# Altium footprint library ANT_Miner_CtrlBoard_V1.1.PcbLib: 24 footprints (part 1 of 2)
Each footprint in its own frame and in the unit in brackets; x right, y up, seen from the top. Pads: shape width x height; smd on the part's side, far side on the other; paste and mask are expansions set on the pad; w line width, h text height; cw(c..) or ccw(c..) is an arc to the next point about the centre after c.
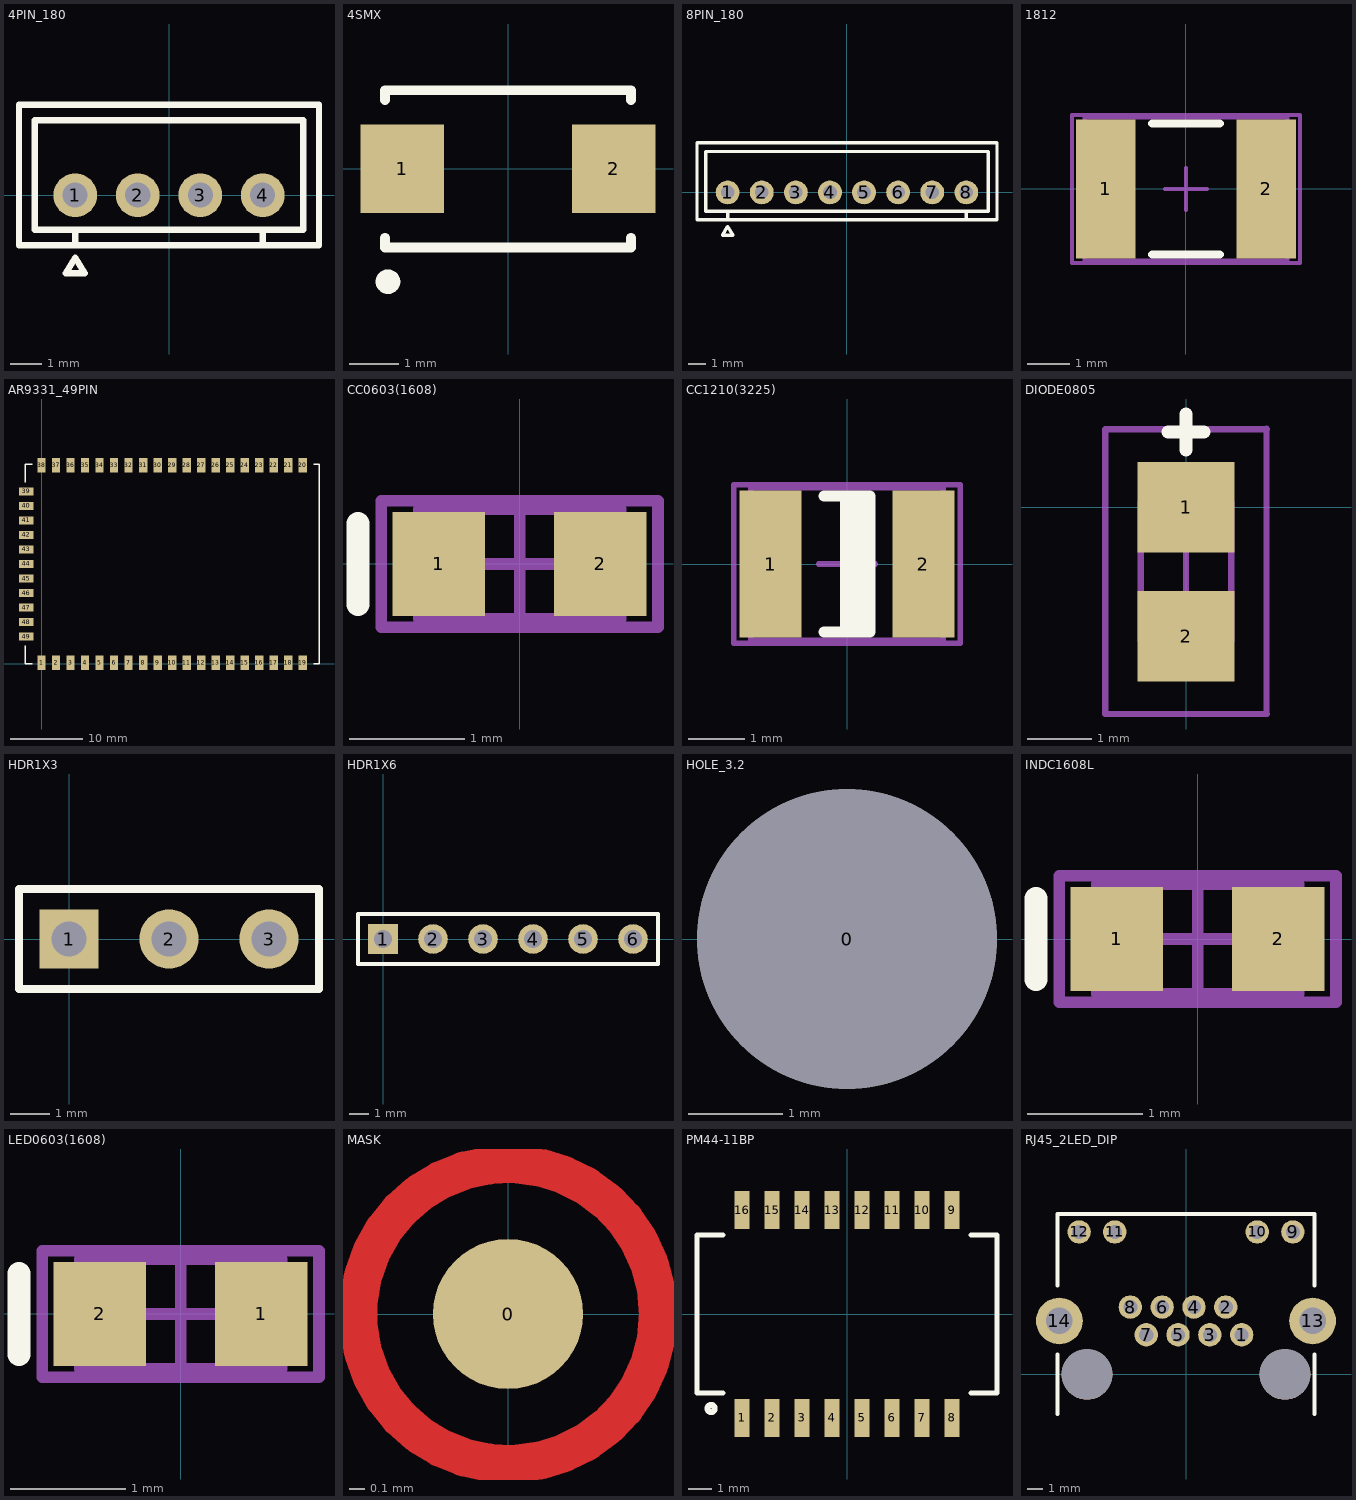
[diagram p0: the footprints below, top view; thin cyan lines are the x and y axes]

## 4PIN_180 [mm]
height 6.8
pads (4):
  round 1.4 hole 0.8: 1(-3,0) 2(-1,0) 3(1,0) 4(3,0)
Top Overlay:
  lines w0.203: -3,-1.6 -3,-1.1 ; 3,-1.6 3,-1.1 ; -4.8,-1.6 4.8,-1.6 4.8,2.9 -4.8,2.9 -4.8,-1.6 ; -4.3,-1.1 4.3,-1.1 4.3,2.4 -4.3,2.4 -4.3,-1.1 ; -3.3,-2.5 -3,-2 -2.7,-2.5 -3.3,-2.5
3D body: height 6.1, standoff -2.2, extent -5,-1.8 5,3

## 4SMX [mm]
height 18.15
pads (2):
  rect 1.7x1.8 smd: 1(-2.15,0) 2(2.15,0)
Top Overlay:
  circle w0.25: c-2.441,-2.293 r0.125
  lines w0.2: -2.5,-1.4 -2.5,-1.6 2.5,-1.6 2.5,-1.4 ; -2.5,1.4 -2.5,1.6 2.5,1.6 2.5,1.4

## 8PIN_180 [mm]
height 6.8
pads (8):
  round 1.4 hole 0.8: 1(-7,0) 2(-5,0) 3(-3,0) 4(-1,0) 5(1,0) 6(3,0) 7(5,0) 8(7,0)
Top Overlay:
  lines w0.203: -7,-1.6 -7,-1.1 ; 7,-1.6 7,-1.1 ; -8.8,-1.6 -8.8,2.9 8.8,2.9 8.8,-1.6 -8.8,-1.6 ; -8.3,-1.1 -8.3,2.4 8.3,2.4 8.3,-1.1 -8.3,-1.1 ; -7.3,-2.5 -6.7,-2.5 -7,-2 -7.3,-2.5
3D body: height 6.1, standoff -2.2, extent -9,-1.8 9,3

## 1812 [mm] "Chip Capacitor, Body 4.5x3.2mm, IPC High Density"
height 1.4
pads (2):
  rect 1.4x3.3 smd: 1(-1.9,0) 2(1.9,0)
Top Overlay:
  lines w0.2: -0.8,-1.55 0.8,-1.55 ; -0.8,1.55 0.8,1.55
Mechanical 13:
  lines w0.1: -2.4,-1.7 2.4,-1.7 2.4,1.7 -2.4,1.7 -2.4,-1.7
Mechanical 15:
  lines w0.1: -0.5,0 0.5,0 ; 0,-0.5 0,0.5 ; -2.7,-1.75 2.7,-1.75 2.7,1.75 -2.7,1.75 -2.7,-1.75
3D body: height 1.4, standoff 0, extent -2.4,-1.7 2.4,1.7

## AR9331_49PIN [mm] "AR9331 49PIN"
height 2.5
pads (49):
  rect 1.143x2 smd: 1(0,0.158) 2(2,0.158) 3(4,0.158) 4(6,0.158) 5(8,0.158) 6(10,0.158) 7(12,0.158) 8(14,0.158) 9(16,0.158) 10(18,0.158) 11(20,0.158) 12(22,0.158) 13(24,0.158) 14(26,0.158) 15(28,0.158) 16(30,0.158) 17(32,0.158) 18(34,0.158) 19(36,0.158) 20(36,27.341) 21(34,27.341) 22(32,27.341) 23(30,27.341) 24(28,27.341) 25(26,27.341) 26(24,27.341) 27(22,27.341) 28(20,27.341) 29(18,27.341) 30(16,27.341) 31(14,27.341) 32(12,27.341) 33(10,27.341) 34(8,27.341) 35(6,27.341) 36(4,27.341) 37(2,27.341) 38(0,27.341)
  rect 2x1.146 smd: 39(-2.11,23.75) 40(-2.11,21.75) 41(-2.11,19.75) 42(-2.11,17.75) 43(-2.11,15.75) 44(-2.11,13.75) 45(-2.11,11.75) 46(-2.11,9.75) 47(-2.11,7.75) 48(-2.11,5.75) 49(-2.11,3.75)
Top Overlay:
  lines w0.203: -2.25,2.5 -2.25,0 -1.25,0 ; -2.25,25 -2.25,27.5 -1.25,27.5 ; 37.5,0 38.25,0 38.25,27.5 37.5,27.5

## CC0603(1608) [mm] "Chip Capacitor, Body 1.6x0.8mm, IPC High Density"
height 0.85
pads (2):
  rect 0.8x0.9 smd: 1(-0.7,0) 2(0.7,0)
Top Overlay:
  lines w0.2: -1.4,-0.35 -1.4,0.35
Mechanical 13:
  lines w0.1: -0.875,-0.475 0.875,-0.475 0.875,0.475 -0.875,0.475 -0.875,-0.475
Mechanical 15:
  lines w0.1: -0.475,0 0.475,0 ; 0,-0.475 0,0.475 ; -1.2,-0.55 1.2,-0.55 1.2,0.55 -1.2,0.55 -1.2,-0.55
3D body: height 0.85, standoff 0, extent -0.875,-0.475 0.875,0.475

## CC1210(3225) [mm] "Chip Capacitor, Body 3.2x2.5mm, IPC High Density"
height 1.35
pads (2):
  rect 1.1x2.6 smd: 1(-1.35,0) 2(1.35,0)
Top Overlay:
  rectangle: -0.125,-1.2 0.425,1.2
  lines w0.2: -0.4,-1.2 0.4,-1.2 0.4,1.2 -0.4,1.2
Mechanical 13:
  lines w0.1: -1.7,-1.35 -1.7,1.35 1.7,1.35 1.7,-1.35 -1.7,-1.35
Mechanical 15:
  lines w0.1: -0.5,0 0.5,0 ; 0,-0.5 0,0.5 ; -2,-1.4 -2,1.4 2,1.4 2,-1.4 -2,-1.4
3D body: height 1.35, standoff 0, extent -1.7,-1.35 1.7,1.35

## DIODE0805 [mm]
height 0.9
pads (2):
  rect 1.5x1.4 smd: 1(0,0) 2(0,-2)
Top Overlay:
  lines w0.203: -0.279,1.159 0.279,1.159 ; 0,0.88 0,1.438
Mechanical 13:
  lines w0.1: -0.7,-2.075 -0.7,0.075 0.7,0.075 0.7,-2.075 -0.7,-2.075
Mechanical 15:
  lines w0.1: 0,-1.5 0,-0.5 ; 1.245,-3.19 1.245,1.21 ; 1.25,-3.2 -1.25,-3.2 -1.25,1.2 1.25,1.2
3D body: height 0.7, standoff 0, extent -0.7,-2.075 0.7,0.075

## HDR1X3 [mm] "Connector; Header; 3 Position"
height 18.15
pads (3):
  rect 1.5x1.5 hole 0.9: 1(0,0)
  round 1.5 hole 0.9: 2(2.54,0) 3(5.08,0)
Top Overlay:
  lines w0.2: -1.27,-1.27 6.35,-1.27 6.35,1.27 -1.27,1.27 -1.27,-1.27

## HDR1X6 [mm] "Connector; Header; 6 Position"
height 18.15
pads (6):
  rect 1.5x1.5 hole 0.9: 1(0,0)
  round 1.5 hole 0.9: 2(2.54,0) 3(5.08,0) 4(7.62,0) 5(10.16,0) 6(12.7,0)
Top Overlay:
  lines w0.2: -1.27,-1.27 -1.27,1.27 13.97,1.27 13.97,-1.27 -1.27,-1.27

## HOLE_3.2 [mm]
pads (1):
  round 3.2 hole 3.2 unplated: 0(4,0)

## INDC1608L [mm] "Chip Inductor, Body 1.6x0.8mm, IPC High Density"
height 0.55
pads (2):
  rect 0.8x0.9 smd: 1(-0.7,0) 2(0.7,0)
Top Overlay:
  lines w0.2: -1.4,-0.35 -1.4,0.35
Mechanical 13:
  lines w0.1: -0.875,-0.475 0.875,-0.475 0.875,0.475 -0.875,0.475 -0.875,-0.475
Mechanical 15:
  lines w0.1: -0.475,0 0.475,0 ; 0,-0.475 0,0.475 ; -1.2,-0.55 1.2,-0.55 1.2,0.55 -1.2,0.55 -1.2,-0.55
3D body: height 0.55, standoff 0, extent -0.875,-0.475 0.875,0.475

## LED0603(1608) [mm] "Chip LED, Body 1.6x0.8mm, IPC High Density"
height 18.15
pads (2):
  rect 0.8x0.9 smd: 1(0.7,0) 2(-0.7,0)
Top Overlay:
  lines w0.2: -1.4,-0.35 -1.4,0.35
Mechanical 13:
  lines w0.1: -0.875,-0.475 -0.875,0.475 0.875,0.475 0.875,-0.475 -0.875,-0.475
Mechanical 15:
  lines w0.1: -0.475,0 0.475,0 ; 0,-0.475 0,0.475 ; -1.2,-0.55 -1.2,0.55 1.2,0.55 1.2,-0.55 -1.2,-0.55
3D body: height 0.85, standoff 0, extent -0.875,-0.475 0.875,0.475

## MASK [mm] "SMD MASK 1mm"
height 18.15
pads (1):
  round 1 smd: 0(0,0)
Top Layer:
  circle w0.254: c0,0 r1
Top Paste:
  circle w0.254: c0,0 r0.508
  circle w1.5: c0,0 r0.508
Top Solder:
  circle w1: c0,0 r0.762

## PM44-11BP [mm]
height 6
pads (16):
  rect 0.64x1.6 smd: 1(-4.445,-4.4) 2(-3.175,-4.4) 3(-1.905,-4.4) 4(-0.635,-4.4) 5(0.635,-4.4) 6(1.905,-4.4) 7(3.175,-4.4) 8(4.445,-4.4) 9(4.445,4.4) 10(3.175,4.4) 11(1.905,4.4) 12(0.635,4.4) 13(-0.635,4.4) 14(-1.905,4.4) 15(-3.175,4.4) 16(-4.445,4.4)
Top Overlay:
  circle w0.254: c-5.75,-4 r0.15
  lines w0.203: -5.25,-3.35 -6.35,-3.35 -6.35,3.35 -5.25,3.35 ; 5.25,-3.35 6.35,-3.35 6.35,3.35 5.25,3.35

## RJ45_2LED_DIP [mm]
height 13.1
pads (16):
  round 1.5 hole 0.9: 1(3.57,2.54) 2(2.55,4.32) 3(1.53,2.54) 4(0.51,4.32) 5(-0.51,2.54) 6(-1.53,4.32) 7(-2.55,2.54) 8(-3.57,4.32) 9(6.86,9.14) 10(4.57,9.14) 11(-4.57,9.14) 12(-6.86,9.14)
  round 3 hole 1.7: 13(8.125,3.43) 14(-8.125,3.43)
  round 3.25 hole 3.25: ""(-6.35,0) ""(6.35,0)
Top Overlay:
  lines w0.254: -8.26,-2.54 -8.26,1.265 -8.255,1.27 ; -8.255,5.715 -8.255,10.29 8.26,10.29 ; 8.255,1.27 8.26,1.265 8.26,-2.54 ; 8.255,5.715 8.255,10.245 8.26,10.25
